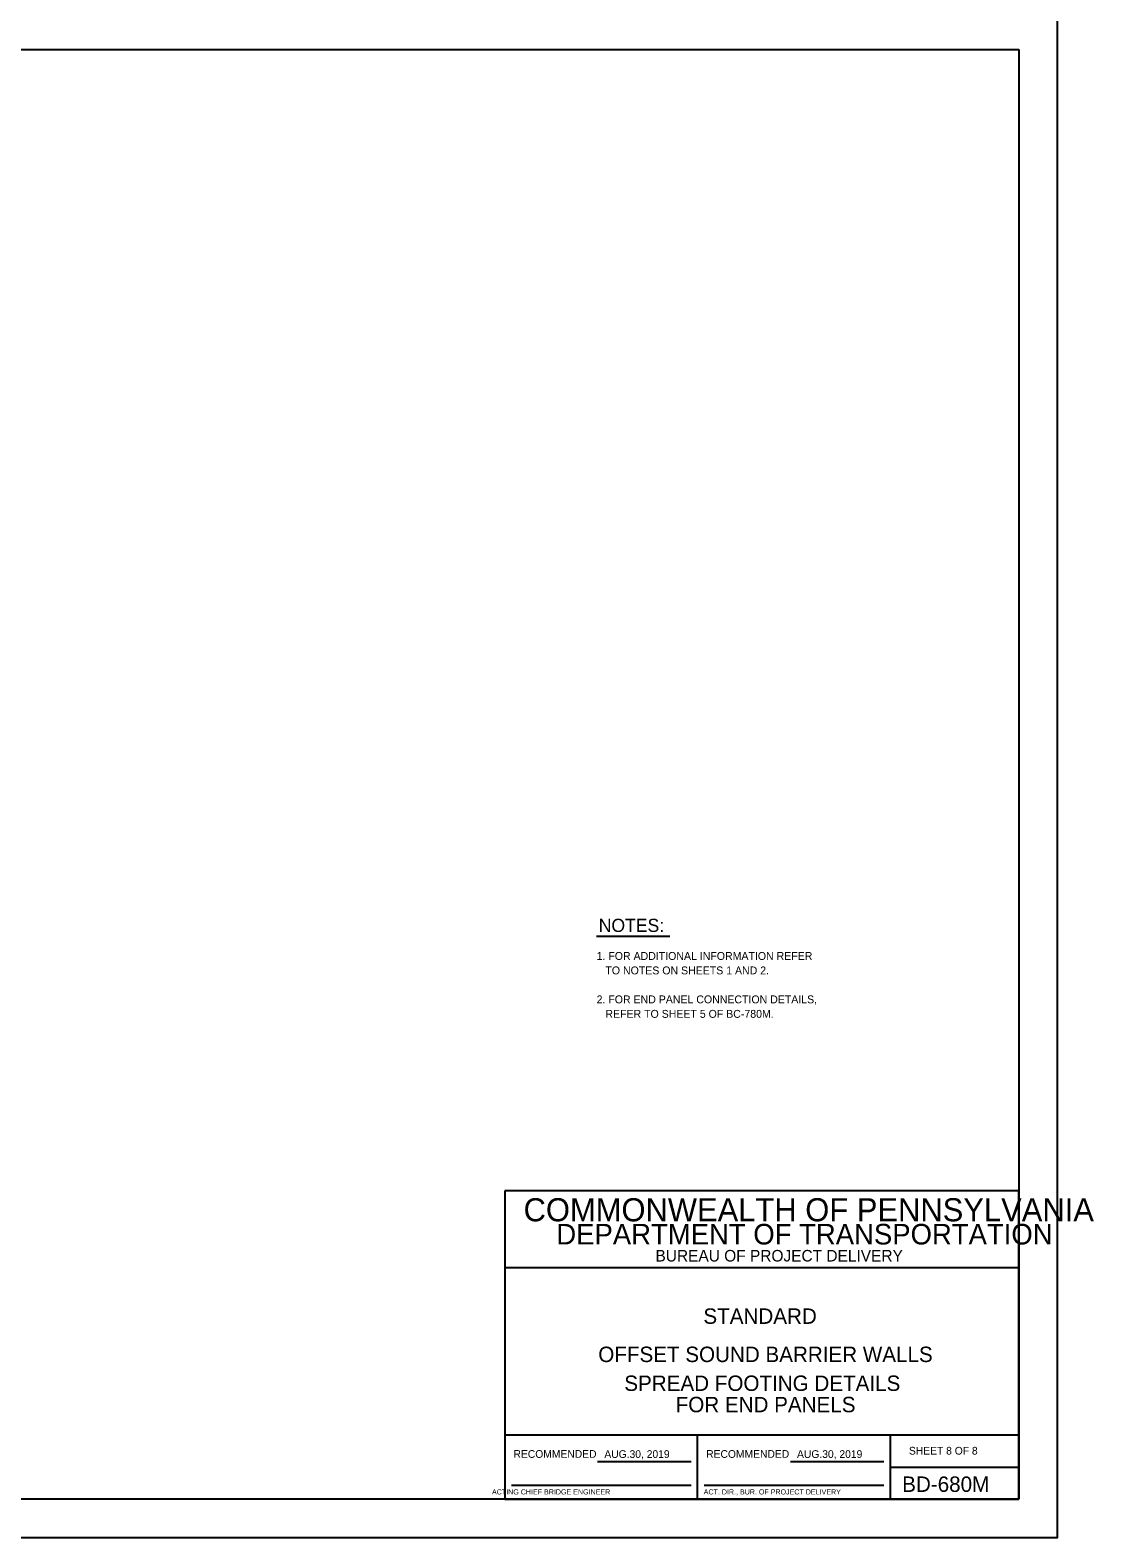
# Model space of a CAD drawing. Extents: x 3385 to 6532, y -616 to 1166.
# Drawn here: x 5885 to 6299, y -616 to -30 of the extents above; entities that cross this region are included whole.
import ezdxf

# ---------------------------------------------------------------- set-up
doc = ezdxf.new("R2010")
doc.units = 0
for name, color, linetype in [('1', 7, 'Continuous'), ('2', 7, 'Continuous'), ('PLT-BNDY', 7, 'Continuous')]:
    doc.layers.add(name, color=color, linetype=linetype)

msp = doc.modelspace()

# ---------------------------------------------------------------- linework, layer by layer
at = {"layer": '1'}
for p, q in [((6105, -382.23), (6133.57, -382.23)), ((6269.34, -601.31), (6269.34, -481.31)), ((6144.34, -601.31), (6144.34, -576.31)), ((6105.43, -586.59), (6141.84, -586.59)), ((6180.43, -586.59), (6216.84, -586.59)), ((6071.84, -595.81), (6141.84, -595.81)), ((6146.84, -595.81), (6216.84, -595.81))]:
    msp.add_line(p, q, dxfattribs=at)
at = {"layer": '2'}
for p, q in [((5483.34, -37.31), (6269.34, -37.31)), ((6269.34, -37.31), (6269.34, -601.31)), ((6269.34, -481.31), (6069.34, -481.31)), ((6069.34, -481.31), (6069.34, -601.31)), ((6269.34, -601.31), (6269.34, -481.31)), ((6269.34, -511.31), (6069.34, -511.31)), ((6269.34, -576.31), (6069.34, -576.31)), ((6219.34, -576.31), (6219.34, -601.31)), ((6219.34, -588.81), (6269.34, -588.81)), ((6269.34, -601.31), (5483.34, -601.31)), ((6069.34, -601.31), (6269.34, -601.31))]:
    msp.add_line(p, q, dxfattribs=at)
at = {"layer": 'PLT-BNDY'}
msp.add_lwpolyline([(5443.34, -22.31), (6284.34, -22.31), (6284.34, -616.31), (5443.34, -616.31)], close=True, dxfattribs=at)

# ---------------------------------------------------------------- texts
at = {"layer": '1'}
for s, height, p in [('NOTES:', 5.117, (6105.84, -380.61)), ('1. FOR ADDITIONAL INFORMATION REFER', 3.072, (6105.02, -391.49)), ('   TO NOTES ON SHEETS 1 AND 2.', 3.072, (6105.02, -397.12)), ('2. FOR END PANEL CONNECTION DETAILS,', 3.072, (6105.02, -408.38)), ('   REFER TO SHEET 5 OF BC-780M.', 3.072, (6105.02, -414.01)), ('STANDARD', 6, (6146.59, -533.06)), ('OFFSET SOUND BARRIER WALLS', 6.0001, (6105.67, -547.93)), ('SPREAD FOOTING DETAILS', 6.0001, (6115.8, -559.16)), ('FOR END PANELS', 6.0001, (6135.8, -567.46)), ('RECOMMENDED', 3, (6072.67, -585.18)), ('AUG.30, 2019', 3, (6108.03, -585.22)), ('RECOMMENDED', 3, (6147.67, -585.18)), ('AUG.30, 2019', 3, (6183.03, -585.22)), ('SHEET 8 OF 8', 3, (6226.59, -583.92)), ('BD-680M', 6, (6223.97, -598.43)), ('       ACTING CHIEF BRIDGE ENGINEER', 2.0002, (6058.93, -599.43)), ('ACT. DIR., BUR. OF PROJECT DELIVERY', 2.0002, (6146.7, -599.43))]:
    msp.add_text(s, height=height, dxfattribs=at).set_placement(p)
at = {"layer": '2'}
for s, height, p in [('COMMONWEALTH OF PENNSYLVANIA', 9, (6076.59, -493.18)), ('DEPARTMENT OF TRANSPORTATION', 8.0002, (6089.34, -502.18)), ('BUREAU OF PROJECT DELIVERY', 4.5, (6127.93, -508.81))]:
    msp.add_text(s, height=height, dxfattribs=at).set_placement(p)

doc.saveas('drawing.dxf')
